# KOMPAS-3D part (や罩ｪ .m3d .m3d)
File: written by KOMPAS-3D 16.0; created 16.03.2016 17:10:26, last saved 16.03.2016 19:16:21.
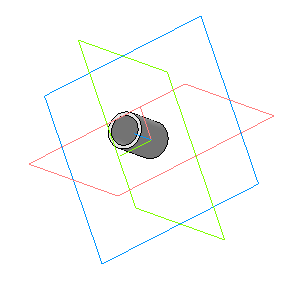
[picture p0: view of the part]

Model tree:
1. Эскиз:1
2. Операция выдавливания:1
     Расстояние 1 = 15; На расстояние 1 = 17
